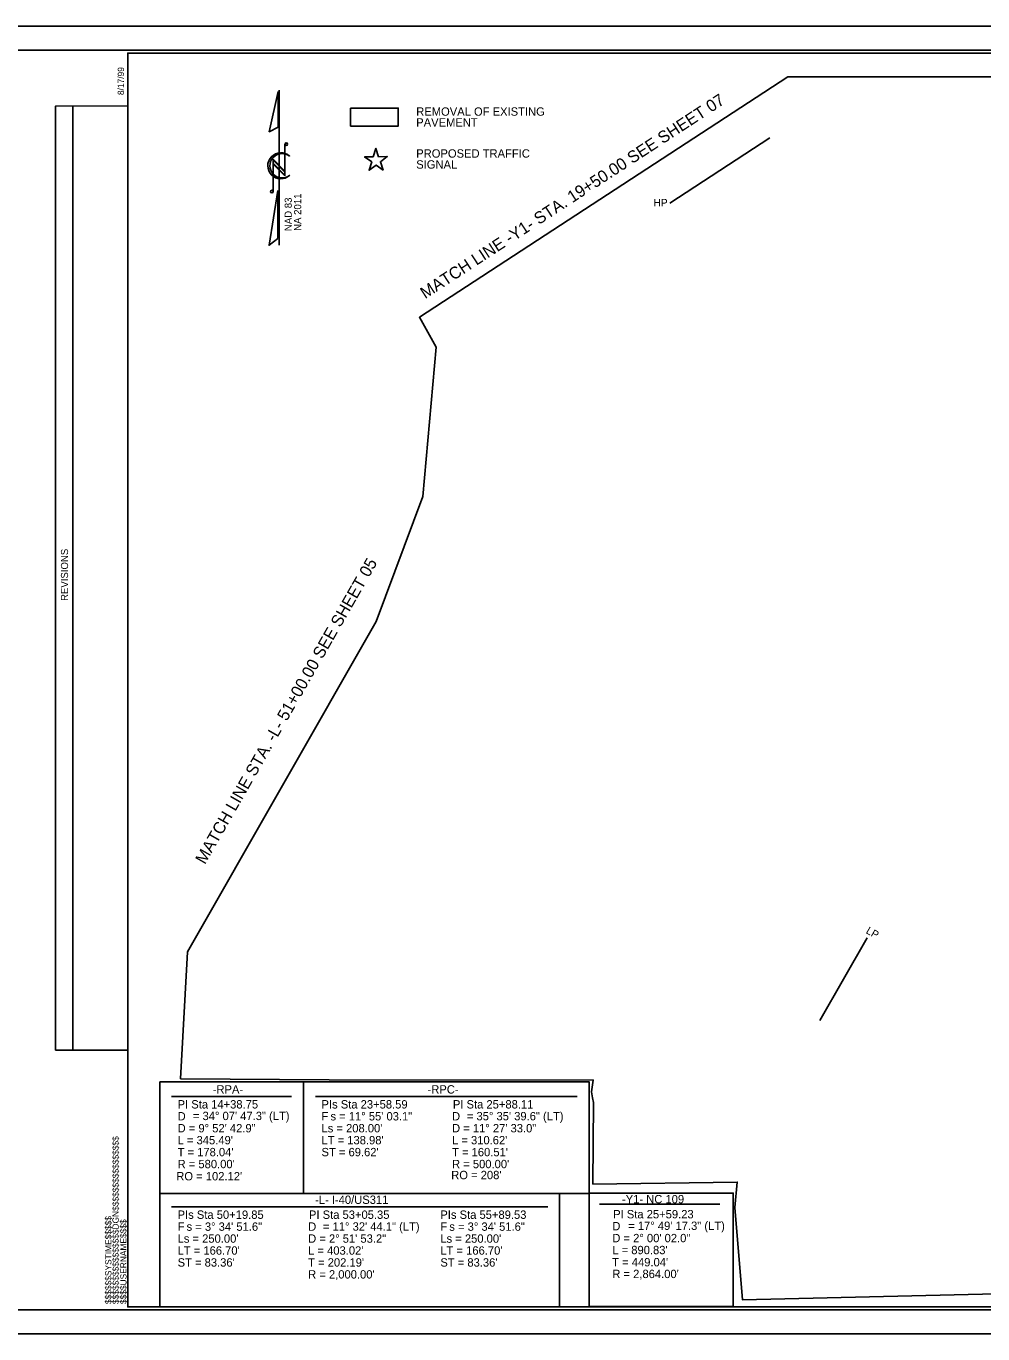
# Model space of a CAD drawing. Extents: x 1639431 to 1641888, y 841916 to 843940.
# Drawn here: x 1640286 to 1641087, y 841916 to 843011 of the extents above; entities that cross this region are included whole.
import ezdxf

# ---------------------------------------------------------------- set-up
doc = ezdxf.new("R2010")
doc.units = 0
for name, color, linetype in [('Matchline', 7, 'Continuous'), ('Matchline Text', 7, 'Continuous'), ('Old_Level_1', 7, 'Continuous'), ('Prop Horizontal Alignment Curve and Spiral Data', 7, 'Continuous'), ('Prop RDY Traffic Signal CELL', 7, 'Continuous'), ('Prop Rem of Exist Asph Pvmt', 7, 'Continuous'), ('Sheet Block Revision CELL', 7, 'Continuous'), ('Sheet Clip Boundary CELL', 7, 'Continuous'), ('Sheet Cutting Line CELL', 7, 'Continuous'), ('Sheet North Arrow CELL', 7, 'Continuous'), ('Sheet Plan CELL', 7, 'Continuous'), ('Sheet Plot Border Inside CELL', 7, 'Continuous'), ('Sheet Plot Border Outside CELL', 7, 'Continuous')]:
    doc.layers.add(name, color=color, linetype=linetype)

msp = doc.modelspace()

# ---------------------------------------------------------------- linework, layer by layer
at = {"layer": 'Matchline'}
msp.add_lwpolyline([(1640420.8, 842236.2), (1640420.8, 842236.2), (1640578.7, 842512.8), (1640617.7, 842617.6), (1640629.1, 842742.4), (1640615, 842767.5), (1640923.5, 842968.8)], dxfattribs=at)
at = {"layer": 'Old_Level_1'}
for p, q in [((1640908.4, 842917.8), (1640824.6, 842863.2)), ((1640950.2, 842178.6), (1640989.8, 842248))]:
    msp.add_line(p, q, dxfattribs=at)
at = {"layer": 'Prop Horizontal Alignment Curve and Spiral Data'}
for p, q in [((1640407.5, 842115), (1640508, 842115)), ((1640528, 842115), (1640747.2, 842115)), ((1640407.5, 842022.6), (1640722.4, 842022.6)), ((1640765.9, 842024.9), (1640866.4, 842024.9))]:
    msp.add_line(p, q, dxfattribs=at)
for points in [[(1640397.5, 842127.2), (1640518, 842127.2), (1640518, 842033.7), (1640397.5, 842033.7)], [(1640518, 842127.2), (1640757.2, 842127.2), (1640757.2, 842033.7), (1640518, 842033.7)], [(1640397.5, 842033.7), (1640732.4, 842033.7), (1640732.4, 841938.8), (1640397.5, 841938.8)], [(1640757.2, 842034.2), (1640877.7, 842034.2), (1640877.7, 841939.3), (1640757.2, 841939.3)]]:
    msp.add_lwpolyline(points, close=True, dxfattribs=at)
at = {"layer": 'Prop RDY Traffic Signal CELL'}
msp.add_lwpolyline([(1640576.3, 842901.9), (1640569.1, 842901.8), (1640575, 842897.6), (1640572.9, 842890.7), (1640578.7, 842895), (1640584.6, 842890.8), (1640582.3, 842897.7), (1640588.1, 842902.1), (1640580.8, 842902), (1640578.5, 842908.9), (1640576.3, 842901.9)], dxfattribs=at)
at = {"layer": 'Prop Rem of Exist Asph Pvmt'}
msp.add_lwpolyline([(1640557.3, 842942.7), (1640557.3, 842927.7), (1640597.3, 842927.7), (1640597.3, 842942.7)], close=True, dxfattribs=at)
at = {"layer": 'Sheet Block Revision CELL'}
msp.add_line((1640324.8, 842153.8), (1640324.8, 842944.5), dxfattribs=at)
msp.add_lwpolyline([(1640310.3, 842153.8), (1640310.3, 842944.4), (1640370.8, 842944.5), (1640370.8, 842153.8)], close=True, dxfattribs=at)
at = {"layer": 'Sheet Clip Boundary CELL'}
msp.add_line((1640923.5, 842968.8), (1641358.9, 842968.8), dxfattribs=at)
for points in [[(1640414.8, 842129.8), (1640420.8, 842236.2), (1640578.7, 842512.8), (1640617.7, 842617.6), (1640629.1, 842742.4), (1640615, 842767.5), (1640923.5, 842968.8)], [(1641627.1, 841958.8), (1641476.3, 841958.8), (1640885.4, 841944.9), (1640879, 842022.1), (1640881.1, 842043.4), (1640760.2, 842041.7), (1640760.7, 842110.1), (1640760, 842113.9), (1640759.1, 842119), (1640760.5, 842128.8), (1640539.4, 842129), (1640414.8, 842129.8)]]:
    msp.add_lwpolyline(points, dxfattribs=at)
at = {"layer": 'Sheet Cutting Line CELL'}
msp.add_line((1640204.3, 841916.3), (1641887.8, 841916.3), dxfattribs=at)
at = {"layer": 'Sheet North Arrow CELL'}
for p, q in [((1640497.5, 842827.8), (1640497.5, 842957.8)), ((1640502.4, 842912.6), (1640502.4, 842885.9)), ((1640502.4, 842890), (1640492.5, 842900)), ((1640492.5, 842900), (1640492.5, 842872.9)), ((1640502.4, 842889.1), (1640492.5, 842899)), ((1640492.5, 842899), (1640492.5, 842896.6)), ((1640506.1, 842902.6), (1640506.3, 842902.5)), ((1640502.4, 842886.6), (1640492.5, 842896.6)), ((1640492.5, 842896.6), (1640502.4, 842886.6)), ((1640502.4, 842885.9), (1640492.5, 842895.8)), ((1640502.4, 842886.6), (1640502.4, 842889.1))]:
    msp.add_line(p, q, dxfattribs=at)
for points in [[(1640496.6, 842956.7), (1640489.2, 842922.9), (1640496.6, 842926.7)], [(1640496.5, 842873.6), (1640489.1, 842827.8), (1640496.5, 842833.6)]]:
    msp.add_lwpolyline(points, close=True, dxfattribs=at)
for centre in [(1640503.5, 842912.5), (1640491.4, 842872.8)]:
    msp.add_circle(centre, 1.06, dxfattribs=at)
for centre, radius, start, end in [((1640498.9, 842894.4), 10.9, 47.84, 312.3941), ((1640500, 842894.4), 10.2, 53.095, 308.6287)]:
    msp.add_arc(centre, radius, start, end, dxfattribs=at)
at = {"layer": 'Sheet Plan CELL'}
for p, q in [((1640370.8, 842988.8), (1640370.8, 842988.8)), ((1640370.8, 841938.8), (1640370.8, 841938.8))]:
    msp.add_line(p, q, dxfattribs=at)
for points in [[(1641870.8, 842988.8), (1640370.8, 842988.8), (1640370.8, 841938.8), (1641870.8, 841938.8)], [(1640370.8, 841938.8), (1640370.8, 842988.8), (1641670.8, 842988.8), (1641670.8, 842838.8), (1641870.8, 842838.8), (1641870.8, 841938.8)]]:
    msp.add_lwpolyline(points, close=True, dxfattribs=at)
at = {"layer": 'Sheet Plot Border Inside CELL'}
msp.add_lwpolyline([(1640217.3, 841936.3), (1641883.3, 841936.3), (1641883.3, 842991.3), (1640217.3, 842991.3)], close=True, dxfattribs=at)
at = {"layer": 'Sheet Plot Border Outside CELL'}
msp.add_lwpolyline([(1640204.3, 841916.3), (1641887.8, 841916.3), (1641887.8, 843011.3), (1640204.3, 843011.3)], close=True, dxfattribs=at)
msp.add_lwpolyline([(1640204.3, 841916.3), (1641887.8, 841916.3), (1641887.8, 843011.3), (1640204.3, 843011.3)], close=True, dxfattribs=at)

# ---------------------------------------------------------------- texts
at = {"layer": 'Matchline Text'}
for s, rotation, p in [('MATCH LINE -Y1- STA. 19+50.00 SEE SHEET 07', 33.1259, (1640619.8, 842782.6)), ('MATCH LINE STA. -L- 51+00.00 SEE SHEET 05', 60.2753, (1640435.4, 842308.8))]:
    msp.add_text(s, height=10, rotation=rotation, dxfattribs=at).set_placement(p)
at = {"layer": 'Old_Level_1'}
msp.add_text('HP', height=6.37, dxfattribs=at).set_placement((1640811, 842860.3))
msp.add_text('LP', height=6.37, rotation=330.2753, dxfattribs=at).set_placement((1640988.3, 842252.1))
at = {"layer": 'Prop Horizontal Alignment Curve and Spiral Data'}
for s, p in [('-RPA-', (1640441.9, 842117.5)), ('-RPC-', (1640621.8, 842117.5)), ('PI Sta 14+38.75', (1640412.5, 842105)), ('PIs Sta 23+58.59', (1640533, 842105)), ('PI Sta 25+88.11', (1640643, 842105)), ('D', (1640412.5, 842095)), ('= 34%%d 07\' 47.3" (LT)', (1640425.3, 842095.3)), ('F', (1640533, 842095)), ('s = 11%%d 55\' 03.1"', (1640540.5, 842095)), ('D', (1640642.3, 842095)), ('= 35%%d 35\' 39.6" (LT)', (1640654.7, 842095.1)), ('D = 9%%d 52\' 42.9"', (1640412.5, 842085)), ("Ls = 208.00'", (1640533, 842085)), ('D = 11%%d 27\' 33.0"', (1640642.3, 842085)), ("L = 345.49'", (1640412.5, 842075)), ("LT = 138.98'", (1640533, 842075)), ("L = 310.62'", (1640642.3, 842075)), ("T = 178.04'", (1640412.5, 842065)), ("ST = 69.62'", (1640533, 842065)), ("T = 160.51'", (1640642.3, 842065)), ("R = 580.00'", (1640412.5, 842055)), ("R = 500.00'", (1640642.3, 842055)), ("RO = 102.12'", (1640411.4, 842044.8)), ("RO = 208'", (1640641.6, 842045.8)), ('-L- I-40/US311', (1640527.6, 842025.1)), ('-Y1- NC 109', (1640784.6, 842025.6)), ('PIs Sta 50+19.85', (1640412.5, 842012.6)), ('PI Sta 53+05.35', (1640522.5, 842012.6)), ('PIs Sta 55+89.53', (1640632.5, 842012.6)), ('PI Sta 25+59.23', (1640777.2, 842013)), ('F', (1640412.5, 842002.6)), ('s = 3%%d 34\' 51.6"', (1640420, 842002.6)), ('D', (1640521.8, 842002.6)), ('= 11%%d 32\' 44.1" (LT)', (1640534.2, 842002.7)), ('F', (1640632.5, 842002.6)), ('s = 3%%d 34\' 51.6"', (1640640, 842002.6)), ('D', (1640776.5, 842003)), ('= 17%%d 49\' 17.3" (LT)', (1640789.8, 842003.3)), ("Ls = 250.00'", (1640412.5, 841992.6)), ("LT = 166.70'", (1640412.5, 841982.6)), ('D = 2%%d 51\' 53.2"', (1640521.8, 841992.6)), ("L = 403.02'", (1640521.8, 841982.6)), ("Ls = 250.00'", (1640632.5, 841992.6)), ("LT = 166.70'", (1640632.5, 841982.6)), ('D = 2%%d 00\' 02.0"', (1640776.5, 841993)), ("L = 890.83'", (1640776.5, 841983)), ("ST = 83.36'", (1640412.5, 841972.6)), ("T = 202.19'", (1640521.8, 841972.6)), ("ST = 83.36'", (1640632.5, 841972.6)), ("T = 449.04'", (1640776.4, 841972.8)), ("R = 2,000.00'", (1640521.8, 841962.6)), ("R = 2,864.00'", (1640776.5, 841963))]:
    msp.add_text(s, height=7, dxfattribs=at).set_placement(p)
at = {"layer": 'Sheet Block Revision CELL'}
msp.add_text('REVISIONS', height=6, rotation=90, dxfattribs=at).set_placement((1640320.8, 842530))
at = {"layer": 'Sheet North Arrow CELL'}
for s, p in [('NAD 83', (1640508.1, 842839.7)), ('NA 2011', (1640516, 842839.9))]:
    msp.add_text(s, height=6, rotation=90, dxfattribs=at).set_placement(p)
at = {"layer": 'Sheet Plan CELL'}
for s, p in [('8/17/99', (1640367.6, 842953.6)), ('$$$$$$$$$$$$$$$$DGN$$$$$$$$$$$$$$$$', (1640363.2, 841941.2)), ('$$$$$$SYSTIME$$$$$', (1640357.1, 841941.2)), ('$$$$USERNAME$$$$', (1640369.7, 841941.2))]:
    msp.add_text(s, height=5.25, rotation=90, dxfattribs=at).set_placement(p)
for s, p in [('REMOVAL OF EXISTING', (1640612.3, 842936.3)), ('PAVEMENT', (1640612.3, 842927.2)), ('SIGNAL', (1640612.3, 842892)), ('PROPOSED TRAFFIC', (1640612.3, 842901.2))]:
    msp.add_text(s, height=7, dxfattribs=at).set_placement(p)

doc.saveas('drawing.dxf')
